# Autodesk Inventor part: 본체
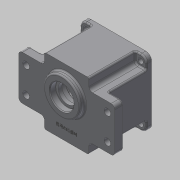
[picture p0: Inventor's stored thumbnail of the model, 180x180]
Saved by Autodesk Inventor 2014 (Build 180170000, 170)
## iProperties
Created: 2014-12
Part Number: 본체
Material: Generic
Document SubType Name: Modeling
Designer: user
Density: 1 g/cm^3
Appearance: Default
Author: user
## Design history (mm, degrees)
sketch "스케치2"
  geometry: L1 (-45, -45)-(45, -45); L2 (45, -45)-(45, 45); L3 (45, 45)-(-45, 45); L4 (-45, 45)-(-45, -45); L5 (-45, -45)-(45, 45); L6 (45, -45)-(-45, 45); 1 further point
  constraints: 12 end point, 2 midpoint, 2 parallel, 1 horizontal, 1 perpendicular
  dimensions: "d0" = 90 distance of L2.end L3.end; "d1" = 90 distance of L1.end L2.end
extrude "돌출1" new body sketch "스케치2" distance "d2" = 70; taper "d3" = 0 deg
sketch "스케치3"
  geometry: L1 (-65, -30)-(65, -30); L2 (65, -30)-(65, 30); L3 (65, 30)-(-65, 30); L4 (-65, 30)-(-65, -30); L5 (-65, -30)-(65, 30); L6 (65, -30)-(-65, 30); 1 further point
  constraints: 12 end point, 2 midpoint, 2 parallel, 1 horizontal, 1 perpendicular
  dimensions: "d4" = 130 distance of L2.end L3.end; "d5" = 60 distance of L1.end L2.end
extrude "돌출2" join sketch "스케치3" distance "d6" = 12; taper "d7" = 0 deg
sketch "스케치4"
  geometry: L1 (-45, 45)-(-30, 45); L2 (-30, 45)-(-30, 30); L3 (-30, 30)-(-45, 30); L4 (-45, 30)-(-45, 45); L5 (45, 45)-(30, 45); L6 (30, 45)-(30, 30); L7 (30, 30)-(45, 30); L8 (45, 30)-(45, 45); L9 (45, -45)-(30, -45); L10 (30, -45)-(30, -30); L11 (30, -30)-(45, -30); L12 (45, -30)-(45, -45); L13 (-45, -45)-(-30, -45); L14 (-30, -45)-(-30, -30); L15 (-30, -30)-(-45, -30); L16 (-45, -30)-(-45, -45); 1 further point
  constraints: 32 end point, 8 parallel, 4 horizontal, 4 perpendicular
  dimensions: "d8" = 15 distance of L1.start L1.end; "d9" = 15 distance of L1.end L2.end; "d10" = 15 distance of L5.start L5.end; "d11" = 15 distance of L5.end L6.end; "d12" = 15 distance of L11.end L9.start; "d13" = 15 distance of L9.start L9.end; "d14" = 15 distance of L13.start L13.end; "d15" = 15 distance of L15.end L13.start
extrude "돌출3" cut sketch "스케치4" distance "d16" = 63; taper "d17" = 0 deg
fillet "모깎기1" dims "d18" = 8
fillet "모깎기2" dims "d19" = 5
fillet "모깎기3" dims "d20" = 2
sketch "스케치5"
  geometry: L1 (-37, -37)-(37, -37); L2 (37, -37)-(37, 37); L3 (37, 37)-(-37, 37); L4 (-37, 37)-(-37, -37); L5 (-37, -37)-(37, 37); L6 (37, -37)-(-37, 37); 5 further points
  constraints: 12 end point, 4 coincident, 2 midpoint, 2 parallel, 1 horizontal, 1 perpendicular
  dimensions: "d21" = 74 distance of L2.end L3.end; "d22" = 74 distance of L1.end L2.end
hole "구멍1" sketch "스케치5" at (-37, 37), (37, 37), (37, -37), (-37, -37) diameter "d23" = 7; stored, may be unused: countersink angle "d27" = 90 deg, drill point angle "d29" = 118 deg; dims "d24" = 6, "d25" = 4, "d26" = 2, "d28" = 8
sketch "스케치6"
  geometry: L1 (-55, -17.5)-(55, -17.5); L2 (55, -17.5)-(55, 17.5); L3 (55, 17.5)-(-55, 17.5); L4 (-55, 17.5)-(-55, -17.5); L5 (-55, -17.5)-(55, 17.5); L6 (55, -17.5)-(-55, 17.5); 5 further points
  constraints: 12 end point, 4 coincident, 2 midpoint, 2 parallel, 1 horizontal, 1 perpendicular
  dimensions: "d30" = 110 distance of L2.end L3.end; "d31" = 35 distance of L1.end L2.end
hole "구멍2" sketch "스케치6" at (-55, 17.5), (-55, -17.5), (55, 17.5), (55, -17.5) diameter "d32" = 9; stored, may be unused: countersink angle "d36" = 90 deg, drill point angle "d38" = 118 deg; dims "d33" = 6, "d34" = 4, "d35" = 2, "d37" = 8
sketch "스케치7"
  geometry: C1 r 25 at (0, 11); 1 further point
  constraints: 1 centre point, 1 vertical alignment
  dimensions: "d39" = 50 diameter of C1; "d40" = 11 distance of point (0, 0) C1.centre
extrude "돌출4" join sketch "스케치7" distance "d41" = 7; taper "d42" = 0 deg
fillet "모깎기4" dims "d43" = 2
sketch "스케치8"
  geometry: C1 r 40 at (0, 0); 1 further point
  constraints: 1 centre point, 1 coincident
  dimensions: "d44" = 80 diameter of C1
extrude "돌출5" cut sketch "스케치8" distance "d45" = 9; taper "d46" = 0 deg
sketch "스케치9"
  geometry: C1 r 40 at (0, 0) reference; C2 r 39 at (0, 0)
  constraints: 1 centre point, 1 coincident
  dimensions: "d47" = 78 diameter of C2
extrude "돌출6" cut sketch "스케치9" distance "d48" = 52; taper "d49" = 0 deg
sketch "스케치10" dims "d50" = 70
  geometry: L1 (24.749, 24.749)-(-24.749, -24.749); L2 (-24.749, 24.749)-(24.749, -24.749); L3 (-35, 0)-(35, 0); C1 r 39 at (0, 0) reference; A1 r 4 centre (24.749, 24.749) between (21.809, 27.462) and (27.462, 21.809); A2 r 4 centre (-24.749, 24.749) between (-27.462, 21.809) and (-21.809, 27.462); A3 r 4 centre (24.749, -24.749) between (27.462, -21.809) and (21.809, -27.462); A4 r 4 centre (-24.749, -24.749) between (-21.809, -27.462) and (-27.462, -21.809); A5 r 3.5 centre (-19.238, -29.836) between (-15.988, -31.135) and (-21.762, -27.412); A6 r 3.5 centre (-29.836, -19.238) between (-31.135, -15.988) and (-32.777, -21.134); A7 r 3.5 centre (19.238, -29.836) between (15.988, -31.135) and (21.134, -32.777); A8 r 3.5 centre (29.836, -19.238) between (27.412, -21.762) and (32.777, -21.134); A9 r 3.5 centre (29.836, 19.238) between (31.135, 15.988) and (32.777, 21.134); A10 r 3.5 centre (19.238, 29.836) between (15.988, 31.135) and (21.762, 27.412); A11 r 3.5 centre (-19.238, 29.836) between (-21.134, 32.777) and (-21.762, 27.412); A12 r 3.5 centre (-29.836, 19.238) between (-27.412, 21.762) and (-32.777, 21.134); A13 r 3.5 centre (-19.238, 29.836) between (-15.988, 31.135) and (-21.134, 32.777); A14 r 3.5 centre (-19.238, 29.836) between (-21.762, 27.412) and (-15.988, 31.135); A15 r 4 centre (-24.749, 24.749) between (-27.577, 27.577) and (-27.462, 21.809); A16 r 3.5 centre (-29.836, 19.238) between (-31.135, 15.988) and (-27.412, 21.762); A17 r 3.5 centre (-29.836, 19.238) between (-32.777, 21.134) and (-31.135, 15.988); A18 r 39 centre (0, 0) between (-32.777, 21.134) and (-32.777, -21.134); A19 r 39 centre (0, 0) between (-21.134, 32.777) and (-32.777, 21.134); A20 r 3.5 centre (19.238, 29.836) between (21.134, 32.777) and (15.988, 31.135); A21 r 3.5 centre (19.238, 29.836) between (21.762, 27.412) and (21.134, 32.777); A22 r 4 centre (24.749, 24.749) between (27.577, 27.577) and (21.809, 27.462); A23 r 4 centre (24.749, 24.749) between (27.462, 21.809) and (27.577, 27.577); A24 r 3.5 centre (29.836, 19.238) between (27.412, 21.762) and (31.135, 15.988); A25 r 3.5 centre (29.836, 19.238) between (32.777, 21.134) and (27.412, 21.762); A26 r 3.5 centre (29.836, -19.238) between (31.135, -15.988) and (27.412, -21.762); A27 r 3.5 centre (29.836, -19.238) between (32.777, -21.134) and (31.135, -15.988); A28 r 4 centre (24.749, -24.749) between (27.577, -27.577) and (27.462, -21.809); A29 r 4 centre (24.749, -24.749) between (21.809, -27.462) and (27.577, -27.577); A30 r 3.5 centre (19.238, -29.836) between (21.762, -27.412) and (15.988, -31.135); A31 r 3.5 centre (19.238, -29.836) between (21.134, -32.777) and (21.762, -27.412); A32 r 39 centre (0, 0) between (21.134, -32.777) and (32.777, -21.134); A33 r 3.5 centre (-19.238, -29.836) between (-21.134, -32.777) and (-15.988, -31.135); A34 r 3.5 centre (-19.238, -29.836) between (-21.762, -27.412) and (-21.134, -32.777); A35 r 4 centre (-24.749, -24.749) between (-27.577, -27.577) and (-21.809, -27.462); A36 r 4 centre (-24.749, -24.749) between (-27.462, -21.809) and (-27.577, -27.577); A37 r 3.5 centre (-29.836, -19.238) between (-27.412, -21.762) and (-31.135, -15.988); A38 r 3.5 centre (-29.836, -19.238) between (-32.777, -21.134) and (-27.412, -21.762); A39 r 39 centre (0, 0) between (-21.134, -32.777) and (21.134, -32.777); A40 r 39 centre (0, 0) between (32.777, -21.134) and (39, 0); A41 r 39 centre (0, 0) between (32.777, 21.134) and (27.577, 27.577); A42 r 39 centre (0, 0) between (39, 0) and (32.777, 21.134); A43 r 39 centre (0, 0) between (27.577, 27.577) and (-21.134, 32.777); A44 r 4 centre (-24.749, 24.749) between (-21.809, 27.462) and (-27.577, 27.577); 3 further points
  constraints: 111 point on circle, 44 centre point, 16 tangent, 7 coincident, 6 end point, 4 midpoint, 1 horizontal, 1 point on line, 35 other
  dimensions: "d51" = 45 deg angle of L3 L1; "d52" = 90 deg angle of L2 L1; "d53" = 8 diameter of A1; "d54" = 8 diameter of A2; "d57" = 8 diameter of A3; "d58" = 8 diameter of A4; "d59" = 7 diameter of A6; "d60" = 7 diameter of A5; "d61" = 7 diameter of A7; "d62" = 7 diameter of A8; "d63" = 7 diameter of A9; "d64" = 7 diameter of A10; "d65" = 7 diameter of A11; "d66" = 7 diameter of A12
extrude "돌출7" join sketch "스케치10" distance "d67" = 52; taper "d68" = 0 deg
sketch "스케치11"
  geometry: A1 r 4 centre (24.749, -24.749) between (27.462, -21.809) and (21.809, -27.462) reference; A2 r 4 centre (-24.749, -24.749) between (-21.809, -27.462) and (-27.462, -21.809) reference; A3 r 4 centre (-24.749, 24.749) between (-27.462, 21.809) and (-21.809, 27.462) reference; A4 r 4 centre (24.749, 24.749) between (21.809, 27.462) and (27.462, 21.809) reference; 4 further points
  constraints: 4 coincident
hole "구멍3" sketch "스케치11" at (-24.749, 24.749), (24.749, 24.749), (24.749, -24.749), (-24.749, -24.749) diameter "d69" = 3.459; stored, may be unused: countersink angle "d73" = 90 deg, drill point angle "d75" = 118 deg; dims "d70" = 12, "d71" = 4, "d72" = 2, "d74" = 15
sketch "스케치12"
  geometry: A1 r 39 centre (0, 0) between (-32.777, 21.134) and (-32.777, -21.134) reference; A2 r 20.5 centre (0, -11) between (-7.402, 8.117) and (7.402, 8.117); A3 r 14 centre (0, 20) between (7.402, 8.117) and (-7.402, 8.117); A4 r 14 centre (0, 20) between (-7.402, 8.117) and (7.402, 8.117); A5 r 20.5 centre (0, -11) between (7.402, 8.117) and (-7.402, 8.117)
  constraints: 8 point on circle, 4 centre point, 2 vertical alignment
  dimensions: "d76" = 41 diameter of A2; "d77" = 28 diameter of A3; "d78" = 11 distance of A1.centre A2.centre; "d79" = 20 distance of A1.centre A3.centre
extrude "돌출8" join sketch "스케치12" distance "d80" = 7; taper "d81" = 0 deg
fillet "모깎기5" dims "d82" = 3
sketch "스케치13"
  geometry: C1 r 17.5 at (0, -11); A1 r 20.5 centre (0, -11) between (-11.115, 6.225) and (11.115, 6.225) reference; 1 further point
  constraints: 1 centre point, 1 coincident
  dimensions: "d83" = 35 diameter of C1
extrude "돌출9" cut sketch "스케치13" distance "d84" = 10; taper "d85" = 0 deg
sketch "스케치14"
  geometry: C1 r 17.5 at (0, 0) reference; C2 r 12.5 at (0, 0); 1 further point
  constraints: 1 centre point, 1 coincident
  dimensions: "d86" = 25 diameter of C2
extrude "돌출10" cut sketch "스케치14" distance "d87" = 5; taper "d88" = 0 deg
sketch "스케치15"
  geometry: C1 r 23 at (0, 0) reference; C2 r 16 at (0, 0); 1 further point
  constraints: 1 centre point, 1 coincident
  dimensions: "d89" = 32 diameter of C2
extrude "돌출11" cut sketch "스케치15" distance "d90" = 8; taper "d91" = 0 deg
chamfer "모따기1" distance "d92" = 1; stored, may be unused: second distance "d93" = 2, angle "d94" = 45 deg
fillet "모깎기6" dims "d95" = 0.3
sketch "스케치16"
  geometry: C1 r 11 at (0, 20); A1 r 14 centre (0, 20) between (10.493, 10.732) and (-10.493, 10.732) reference; 1 further point
  constraints: 1 centre point, 1 coincident
  dimensions: "d96" = 22 diameter of C1
extrude "돌출12" cut sketch "스케치16" distance "d97" = 7; taper "d98" = 0 deg
sketch "스케치17"
  geometry: C1 r 11 at (0, 0) reference; C2 r 9.5 at (0, 0); 1 further point
  constraints: 1 centre point, 1 coincident
  dimensions: "d99" = 19 diameter of C2
extrude "돌출13" cut sketch "스케치17" distance "d100" = 1; taper "d101" = 0 deg
fillet "모깎기7" dims "d102" = 2
fillet "모깎기8" dims "d103" = 0.3
fillet "모깎기9" dims "d104" = 2
chamfer "모따기2" distance "d105" = 1; stored, may be unused: second distance "d106" = 2, angle "d107" = 45 deg
sketch "스케치18"
  geometry: L1 (-28, -45)-(28, -45) reference; C1 r 27 at (0, 11) reference; 2 further points
  constraints: 1 vertical alignment, 1 other
  dimensions: "d108" = 15 distance from line of L1 point (0, -30)
feature "엠보싱1" sketch "스케치18" dims "d0" = 90, "d1" = 90, "d109" = 0.5, "d110" = 0
node "솔리드1"
